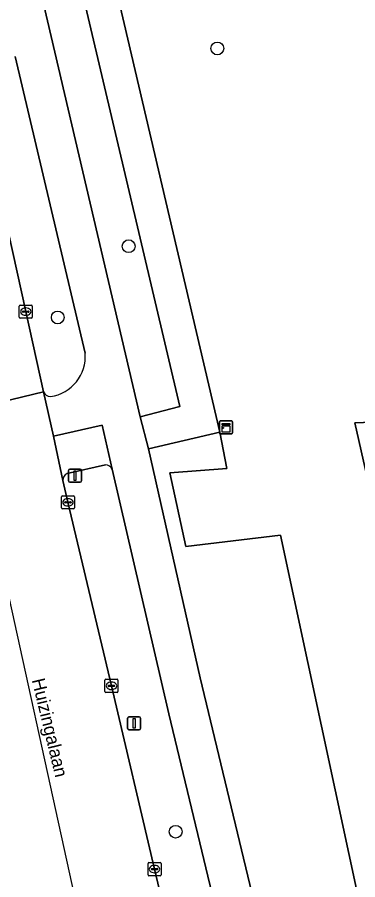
# Model space of a CAD drawing. Extents: x 159451 to 160664, y 388402 to 389723.
# Drawn here: x 159567.1 to 159593.2, y 388627.6 to 388693.5 of the extents above; entities that cross this region are included whole.
import ezdxf

# ---------------------------------------------------------------- set-up
doc = ezdxf.new("R2010")
doc.units = 0
for name, color, linetype in [('IMGEO_Berm_groen', 7, 'Continuous'), ('IMGEO_Boom', 7, 'Continuous'), ('IMGEO_Fietspad_gesloten', 7, 'Continuous'), ('IMGEO_Groenvoorziening', 7, 'Continuous'), ('IMGEO_Kast', 7, 'Continuous'), ('IMGEO_Kolk', 7, 'Continuous'), ('IMGEO_Lichtmast', 7, 'Continuous'), ('IMGEO_Openbare_ruimte_label', 7, 'Continuous'), ('IMGEO_Rijbaan_regionaal_gesloten', 7, 'Continuous'), ('IMGEO_Verkeerseiland_groen', 7, 'Continuous'), ('IMGEO_Verkeersregelinstallatiepaal', 7, 'Continuous'), ('IMGEO_Voetpad_open', 7, 'Continuous')]:
    doc.layers.add(name, color=color, linetype=linetype)

msp = doc.modelspace()

# ---------------------------------------------------------------- linework, layer by layer
at = {"layer": 'IMGEO_Berm_groen'}
msp.add_lwpolyline([(159568.624, 388696.886), (159576.544, 388662.982), (159579.591, 388663.756), (159571.616, 388697.547)], close=True, dxfattribs=at)
for points in [[(159573.898, 388659.307), (159570.961, 388658.636)], [(159631.158, 388402.502), (159635.066, 388402.93), (159633.14, 388411.125), (159628.643, 388429.97), (159623.96, 388449.846), (159619.346, 388469.16), (159614.917, 388487.946), (159610.308, 388507.337), (159605.503, 388527.843), (159601.008, 388546.724), (159596.625, 388565.41), (159591.677, 388586.33), (159588.042, 388601.633), (159586.471, 388608.09), (159578.73, 388640.269), (159574.415, 388658.968)], [(159570.633, 388658.101), (159571.024, 388656.438), (159574.351, 388642.401), (159577.648, 388628.377), (159581.224, 388613.369), (159582.811, 388606.665), (159584.56, 388599.332), (159587.885, 388585.285), (159592.584, 388565.421), (159597.305, 388545.532), (159601.628, 388527.198), (159606.488, 388506.749), (159611.175, 388486.873), (159615.662, 388467.928), (159620.128, 388449.034), (159624.859, 388429.159), (159629.318, 388410.257), (159631.158, 388402.502)]]:
    msp.add_lwpolyline(points, dxfattribs=at)
for centre, radius, start, end in [((159573.898, 388658.743), 0.564, 23.52553, 89.96828), ((159571.159, 388658.146), 0.528, 112.06059, 184.91581)]:
    msp.add_arc(centre, radius, start, end, dxfattribs=at)
at = {"layer": 'IMGEO_Boom'}
for centre in [(159582.447, 388691.159), (159575.671, 388676.03), (159570.243, 388670.579), (159579.258, 388631.237)]:
    msp.add_circle(centre, 0.489, dxfattribs=at)
at = {"layer": 'IMGEO_Fietspad_gesloten'}
for points in [[(159638.028, 388403.254), (159636.049, 388411.652), (159631.399, 388431.147), (159626.817, 388450.4), (159622.428, 388468.978), (159617.766, 388488.657), (159613.26, 388507.823), (159608.335, 388528.706), (159603.765, 388547.95), (159598.928, 388568.512), (159594.52, 388587.297), (159590.61, 388603.644), (159589.369, 388608.734), (159581.133, 388643.019), (159577.172, 388660.52), (159576.544, 388662.982), (159568.624, 388696.886), (159568.102, 388698.902), (159567.82, 388699.99), (159564.809, 388699.667), (159565.107, 388698.419), (159565.609, 388696.315), (159562.402, 388695.607), (159563.101, 388692.202)], [(159566.996, 388690.549), (159572.338, 388667.842)], [(159569.16, 388664.889), (159569.913, 388661.5), (159573.643, 388662.34), (159574.415, 388658.968), (159578.73, 388640.269), (159586.471, 388608.09), (159588.042, 388601.633), (159591.677, 388586.33), (159596.625, 388565.41), (159601.008, 388546.724), (159605.503, 388527.843), (159610.308, 388507.337), (159614.917, 388487.946), (159619.346, 388469.16), (159623.96, 388449.846), (159628.643, 388429.97), (159633.14, 388411.125), (159635.066, 388402.93), (159638.028, 388403.254)]]:
    msp.add_lwpolyline(points, dxfattribs=at)
for centre, radius, start, end in [((159569.262, 388667.587), 3.086, 277.89338, 4.73639), ((159569.684, 388665.092), 0.562, 201.15545, 270.21674)]:
    msp.add_arc(centre, radius, start, end, dxfattribs=at)
at = {"layer": 'IMGEO_Groenvoorziening'}
for points in [[(159574.09, 388698.317), (159582.628, 388661.796), (159583.172, 388659.02), (159578.816, 388658.684), (159580.037, 388653.046), (159587.271, 388653.938), (159607.055, 388561.755), (159631.299, 388467.946), (159635.077, 388466.751), (159633.653, 388472.485), (159631.061, 388473.682), (159616.085, 388536.331), (159613.149, 388550.613), (159628.94, 388549.645), (159634.59, 388545.573), (159639.529, 388542.112), (159640.802, 388543.248), (159639.463, 388544.643), (159637.242, 388548.589), (159634.86, 388555.782), (159632.799, 388565.08), (159630.192, 388578.848), (159627.18, 388593.996)], [(159611.363, 388621.757), (159610.052, 388628.478), (159608.339, 388633.739), (159606.749, 388638.389), (159605.526, 388639.679), (159604.405, 388638.962), (159601.866, 388639.544), (159599.755, 388643.337), (159598.856, 388644.869), (159596.889, 388651.549), (159594.279, 388662.568), (159592.966, 388662.518), (159595.684, 388650.454), (159598.603, 388640.324), (159600.643, 388636.335), (159603.293, 388635.791), (159604.46, 388631.854), (159605.048, 388627.034)], [(159595.684, 388650.454), (159592.966, 388662.518), (159594.279, 388662.568)], [(159631.299, 388467.946), (159607.055, 388561.755), (159587.271, 388653.938), (159580.037, 388653.046), (159578.816, 388658.684), (159583.172, 388659.02), (159582.628, 388661.796), (159577.172, 388660.52), (159581.133, 388643.019), (159589.369, 388608.734), (159590.61, 388603.644), (159594.52, 388587.297), (159598.928, 388568.512), (159603.765, 388547.95), (159608.335, 388528.706), (159613.26, 388507.823), (159617.766, 388488.657)]]:
    msp.add_lwpolyline(points, dxfattribs=at)
at = {"layer": 'IMGEO_Kast'}
for p, q in [((159582.613, 388661.743), (159582.613, 388662.584)), ((159582.613, 388662.584), (159582.613, 388661.743)), ((159582.688, 388662.668), (159583.529, 388662.668)), ((159583.529, 388662.668), (159582.688, 388662.668)), ((159583.613, 388662.593), (159583.613, 388661.752)), ((159583.613, 388661.752), (159583.613, 388662.593)), ((159583.538, 388661.668), (159582.697, 388661.668)), ((159582.697, 388661.668), (159583.538, 388661.668))]:
    msp.add_line(p, q, dxfattribs=at)
for points in [[(159582.808, 388662.458), (159583.408, 388662.458), (159583.408, 388662.373), (159582.808, 388662.373), (159582.808, 388662.458)], [(159582.808, 388662.283), (159583.408, 388662.283), (159583.408, 388661.794), (159582.808, 388661.794), (159582.808, 388662.283)]]:
    msp.add_lwpolyline(points, dxfattribs=at)
msp.add_circle((159582.892, 388662.132), 0.0377, dxfattribs=at)
for centre, start, end in [((159582.691, 388662.59), 92.4484, 184.28452), ((159582.691, 388662.59), 92.4484, 184.28452), ((159583.535, 388662.59), 2.4484, 94.28452), ((159583.535, 388662.59), 2.4484, 94.28452), ((159582.691, 388661.746), 182.4484, 274.28452), ((159582.691, 388661.746), 182.4484, 274.28452), ((159583.535, 388661.746), 272.4484, 4.28452), ((159583.535, 388661.746), 272.4484, 4.28452)]:
    msp.add_arc(centre, 0.0779, start, end, dxfattribs=at)
at = {"layer": 'IMGEO_Kolk'}
for p, q in [((159567.297, 388670.598), (159567.297, 388671.45)), ((159567.372, 388671.524), (159568.224, 388671.524)), ((159568.298, 388671.45), (159568.298, 388670.598)), ((159567.556, 388671.018), (159567.556, 388671.03)), ((159567.994, 388670.981), (159567.596, 388670.981)), ((159567.599, 388671.067), (159567.997, 388671.067)), ((159567.808, 388670.744), (159567.783, 388670.744)), ((159567.785, 388671.304), (159567.81, 388671.304)), ((159568.04, 388671.03), (159568.04, 388671.018)), ((159568.224, 388670.524), (159567.372, 388670.524)), ((159570.523, 388656.012), (159570.523, 388656.864)), ((159570.598, 388656.938), (159571.45, 388656.938)), ((159571.524, 388656.864), (159571.524, 388656.012)), ((159570.782, 388656.432), (159570.782, 388656.444)), ((159571.22, 388656.395), (159570.822, 388656.395)), ((159570.825, 388656.481), (159571.223, 388656.481)), ((159571.034, 388656.158), (159571.009, 388656.158)), ((159571.011, 388656.718), (159571.036, 388656.718)), ((159571.266, 388656.444), (159571.266, 388656.432)), ((159571.45, 388655.938), (159570.598, 388655.938)), ((159573.85, 388641.975), (159573.85, 388642.827)), ((159573.925, 388642.901), (159574.777, 388642.901)), ((159574.109, 388642.395), (159574.109, 388642.407)), ((159574.547, 388642.358), (159574.149, 388642.358)), ((159574.152, 388642.444), (159574.55, 388642.444)), ((159574.338, 388642.681), (159574.363, 388642.681)), ((159574.593, 388642.407), (159574.593, 388642.395)), ((159574.851, 388642.827), (159574.851, 388641.975)), ((159574.777, 388641.901), (159573.925, 388641.901)), ((159574.361, 388642.121), (159574.336, 388642.121)), ((159577.147, 388627.951), (159577.147, 388628.803)), ((159577.222, 388628.877), (159578.074, 388628.877)), ((159577.635, 388628.657), (159577.66, 388628.657)), ((159578.148, 388628.803), (159578.148, 388627.951)), ((159578.074, 388627.877), (159577.222, 388627.877)), ((159577.406, 388628.371), (159577.406, 388628.383)), ((159577.844, 388628.334), (159577.446, 388628.334)), ((159577.449, 388628.42), (159577.847, 388628.42)), ((159577.658, 388628.097), (159577.633, 388628.097)), ((159577.89, 388628.383), (159577.89, 388628.371))]:
    msp.add_line(p, q, dxfattribs=at)
for points in [[(159567.297, 388670.598), (159567.297, 388671.45)], [(159567.372, 388671.524), (159568.224, 388671.524)], [(159568.298, 388671.45), (159568.298, 388670.598)], [(159568.224, 388670.524), (159567.372, 388670.524)], [(159570.523, 388656.012), (159570.523, 388656.864)], [(159570.598, 388656.938), (159571.45, 388656.938)], [(159571.524, 388656.864), (159571.524, 388656.012)], [(159571.45, 388655.938), (159570.598, 388655.938)], [(159573.85, 388641.975), (159573.85, 388642.827)], [(159573.925, 388642.901), (159574.777, 388642.901)], [(159574.851, 388642.827), (159574.851, 388641.975)], [(159574.777, 388641.901), (159573.925, 388641.901)], [(159577.147, 388627.951), (159577.147, 388628.803)], [(159577.222, 388628.877), (159578.074, 388628.877)], [(159578.148, 388628.803), (159578.148, 388627.951)], [(159578.074, 388627.877), (159577.222, 388627.877)]]:
    msp.add_lwpolyline(points, dxfattribs=at)
for centre, radius, start, end in [((159567.374, 388671.448), 0.0765, 91.55205, 178.44795), ((159567.374, 388671.448), 0.0765, 91.55205, 178.44795), ((159568.222, 388671.448), 0.0765, 1.55205, 88.44795), ((159568.222, 388671.448), 0.0765, 1.55205, 88.44795), ((159567.596, 388671.027), 0.0403, 85.87752, 175.75265), ((159567.593, 388671.017), 0.0366, 178.93798, 274.71019), ((159567.997, 388671.024), 0.043, 264.86636, 352.45326), ((159568.001, 388671.029), 0.0386, 1.73085, 96.63898), ((159567.374, 388670.6), 0.0765, 181.55205, 268.44795), ((159567.374, 388670.6), 0.0765, 181.55205, 268.44795), ((159568.222, 388670.6), 0.0765, 271.55205, 358.44795), ((159568.222, 388670.6), 0.0765, 271.55205, 358.44795), ((159570.6, 388656.862), 0.0765, 91.55205, 178.44795), ((159570.6, 388656.862), 0.0765, 91.55205, 178.44795), ((159571.448, 388656.862), 0.0765, 1.55205, 88.44795), ((159571.448, 388656.862), 0.0765, 1.55205, 88.44795), ((159570.822, 388656.441), 0.0403, 85.87752, 175.75265), ((159570.819, 388656.431), 0.0366, 178.93798, 274.71019), ((159571.223, 388656.438), 0.043, 264.86636, 352.45326), ((159571.227, 388656.443), 0.0386, 1.73085, 96.63898), ((159570.6, 388656.014), 0.0765, 181.55205, 268.44795), ((159570.6, 388656.014), 0.0765, 181.55205, 268.44795), ((159571.448, 388656.014), 0.0765, 271.55205, 358.44795), ((159571.448, 388656.014), 0.0765, 271.55205, 358.44795), ((159573.927, 388642.825), 0.0765, 91.55205, 178.44795), ((159573.927, 388642.825), 0.0765, 91.55205, 178.44795), ((159574.149, 388642.404), 0.0403, 85.87752, 175.75265), ((159574.146, 388642.394), 0.0366, 178.93798, 274.71019), ((159574.55, 388642.401), 0.043, 264.86636, 352.45326), ((159574.554, 388642.406), 0.0386, 1.73085, 96.63898), ((159574.775, 388642.825), 0.0765, 1.55205, 88.44795), ((159574.775, 388642.825), 0.0765, 1.55205, 88.44795), ((159573.927, 388641.977), 0.0765, 181.55205, 268.44795), ((159573.927, 388641.977), 0.0765, 181.55205, 268.44795), ((159574.775, 388641.977), 0.0765, 271.55205, 358.44795), ((159574.775, 388641.977), 0.0765, 271.55205, 358.44795), ((159577.224, 388628.801), 0.0765, 91.55205, 178.44795), ((159577.224, 388628.801), 0.0765, 91.55205, 178.44795), ((159578.072, 388628.801), 0.0765, 1.55205, 88.44795), ((159578.072, 388628.801), 0.0765, 1.55205, 88.44795), ((159577.224, 388627.953), 0.0765, 181.55205, 268.44795), ((159577.224, 388627.953), 0.0765, 181.55205, 268.44795), ((159577.446, 388628.38), 0.0403, 85.87752, 175.75265), ((159577.443, 388628.37), 0.0366, 178.93798, 274.71019), ((159577.847, 388628.377), 0.043, 264.86636, 352.45326), ((159577.851, 388628.382), 0.0386, 1.73085, 96.63898), ((159578.072, 388627.953), 0.0765, 271.55205, 358.44795), ((159578.072, 388627.953), 0.0765, 271.55205, 358.44795)]:
    msp.add_arc(centre, radius, start, end, dxfattribs=at)
for centre, major_axis, ratio, start_param, end_param in [((159567.784, 388671.024), (-0.387, 0.002), 0.722429, 4.712389, 7.853982), ((159567.809, 388671.024), (-0.39, 0.002), 0.717154, 1.570796, 4.712389), ((159571.01, 388656.438), (-0.387, 0.002), 0.722429, 4.712389, 7.853982), ((159571.035, 388656.438), (-0.39, 0.002), 0.717154, 1.570796, 4.712389), ((159574.337, 388642.401), (-0.387, 0.002), 0.722429, 4.712389, 7.853982), ((159574.362, 388642.401), (-0.39, 0.002), 0.717154, 1.570796, 4.712389), ((159577.634, 388628.377), (-0.387, 0.002), 0.722429, 4.712389, 7.853982), ((159577.659, 388628.377), (-0.39, 0.002), 0.717154, 1.570796, 4.712389)]:
    msp.add_ellipse(centre, major_axis=major_axis, ratio=ratio, start_param=start_param, end_param=end_param, dxfattribs=at)
at = {"layer": 'IMGEO_Lichtmast'}
for p, q in [((159575.588, 388639.13), (159575.588, 388639.93)), ((159575.588, 388639.93), (159575.588, 388639.13)), ((159575.688, 388640.03), (159576.478, 388640.03)), ((159576.478, 388640.03), (159575.688, 388640.03)), ((159576.578, 388639.93), (159576.578, 388639.13)), ((159576.578, 388639.13), (159576.578, 388639.93)), ((159576.478, 388639.03), (159575.688, 388639.03)), ((159575.688, 388639.03), (159576.478, 388639.03))]:
    msp.add_line(p, q, dxfattribs=at)
msp.add_lwpolyline([(159576.008, 388639.905), (159576.158, 388639.905), (159576.158, 388639.155), (159576.008, 388639.155), (159576.008, 388639.905)], dxfattribs=at)
for centre, start, end in [((159575.688, 388639.93), 90, 180), ((159575.688, 388639.93), 90, 180), ((159576.478, 388639.93), 0, 90), ((159576.478, 388639.93), 360, 90), ((159575.688, 388639.13), 180, 270), ((159575.688, 388639.13), 180, 270), ((159576.478, 388639.13), 270, 0), ((159576.478, 388639.13), 270, 0)]:
    msp.add_arc(centre, 0.1, start, end, dxfattribs=at)
at = {"layer": 'IMGEO_Rijbaan_regionaal_gesloten'}
for points in [[(159563.338, 388663.486), (159569.16, 388664.889), (159567.798, 388671.024), (159564.462, 388686.08), (159563.101, 388692.202), (159562.402, 388695.607), (159561.983, 388697.35), (159561.591, 388698.976), (159561.065, 388701.196), (159560.622, 388703.147), (159556.369, 388721.14), (159551.719, 388741.019), (159547.279, 388759.928), (159546.643, 388762.611), (159542.655, 388780.781), (159538.44, 388800.319), (159534.259, 388820.292), (159530.218, 388840.264), (159526.532, 388859.301)], [(159606.488, 388506.749), (159601.628, 388527.198), (159597.305, 388545.532), (159592.584, 388565.421), (159587.885, 388585.285), (159584.56, 388599.332), (159582.811, 388606.665), (159581.224, 388613.369), (159577.648, 388628.377), (159574.351, 388642.401), (159571.024, 388656.438), (159570.633, 388658.101), (159569.913, 388661.5), (159569.16, 388664.889), (159563.338, 388663.486), (159573.647, 388616.631), (159576.08, 388606.453), (159577.488, 388600.931), (159578.31, 388597.987), (159580.367, 388591.586), (159581.123, 388589.469), (159584.612, 388580.367)]]:
    msp.add_lwpolyline(points, dxfattribs=at)
at = {"layer": 'IMGEO_Verkeerseiland_groen'}
for points in [[(159563.101, 388692.202), (159564.462, 388686.08), (159567.798, 388671.024), (159569.16, 388664.889)], [(159572.338, 388667.842), (159566.996, 388690.549)]]:
    msp.add_lwpolyline(points, dxfattribs=at)
for centre, radius, start, end in [((159569.262, 388667.587), 3.086, 277.89338, 4.73639), ((159569.684, 388665.092), 0.562, 201.15545, 270.21674)]:
    msp.add_arc(centre, radius, start, end, dxfattribs=at)
at = {"layer": 'IMGEO_Verkeersregelinstallatiepaal'}
for p, q in [((159571.067, 388658.072), (159571.067, 388658.872)), ((159571.067, 388658.872), (159571.067, 388658.072)), ((159571.167, 388658.972), (159571.957, 388658.972)), ((159571.957, 388658.972), (159571.167, 388658.972)), ((159572.057, 388658.872), (159572.057, 388658.072)), ((159572.057, 388658.072), (159572.057, 388658.872)), ((159571.957, 388657.972), (159571.167, 388657.972)), ((159571.167, 388657.972), (159571.957, 388657.972))]:
    msp.add_line(p, q, dxfattribs=at)
msp.add_lwpolyline([(159571.487, 388658.847), (159571.637, 388658.847), (159571.637, 388658.097), (159571.487, 388658.097), (159571.487, 388658.847)], dxfattribs=at)
for centre, start, end in [((159571.167, 388658.872), 90, 180), ((159571.167, 388658.872), 90, 180), ((159571.957, 388658.872), 0, 90), ((159571.957, 388658.872), 360, 90), ((159571.167, 388658.072), 180, 270), ((159571.167, 388658.072), 180, 270), ((159571.957, 388658.072), 270, 0), ((159571.957, 388658.072), 270, 0)]:
    msp.add_arc(centre, 0.1, start, end, dxfattribs=at)
at = {"layer": 'IMGEO_Voetpad_open'}
msp.add_lwpolyline([(159574.09, 388698.317), (159573.638, 388700.252), (159573.34, 388701.526), (159570.89, 388700.665), (159567.82, 388699.99), (159568.102, 388698.902), (159568.624, 388696.886), (159571.616, 388697.547), (159579.591, 388663.756), (159576.544, 388662.982), (159577.172, 388660.52), (159582.628, 388661.796)], close=True, dxfattribs=at)
for points in [[(159574.415, 388658.968), (159573.643, 388662.34), (159569.913, 388661.5)], [(159569.913, 388661.5), (159570.633, 388658.101)], [(159570.961, 388658.636), (159573.898, 388659.307)]]:
    msp.add_lwpolyline(points, dxfattribs=at)
for centre, radius, start, end in [((159573.898, 388658.743), 0.564, 23.52553, 89.96828), ((159571.159, 388658.146), 0.528, 112.06059, 184.91581)]:
    msp.add_arc(centre, radius, start, end, dxfattribs=at)

# ---------------------------------------------------------------- texts
at = {"layer": 'IMGEO_Openbare_ruimte_label'}
msp.add_text('Huizingalaan', height=1, rotation=283.59156, dxfattribs=at).set_placement((159568.252, 388642.846))

doc.saveas('drawing.dxf')
